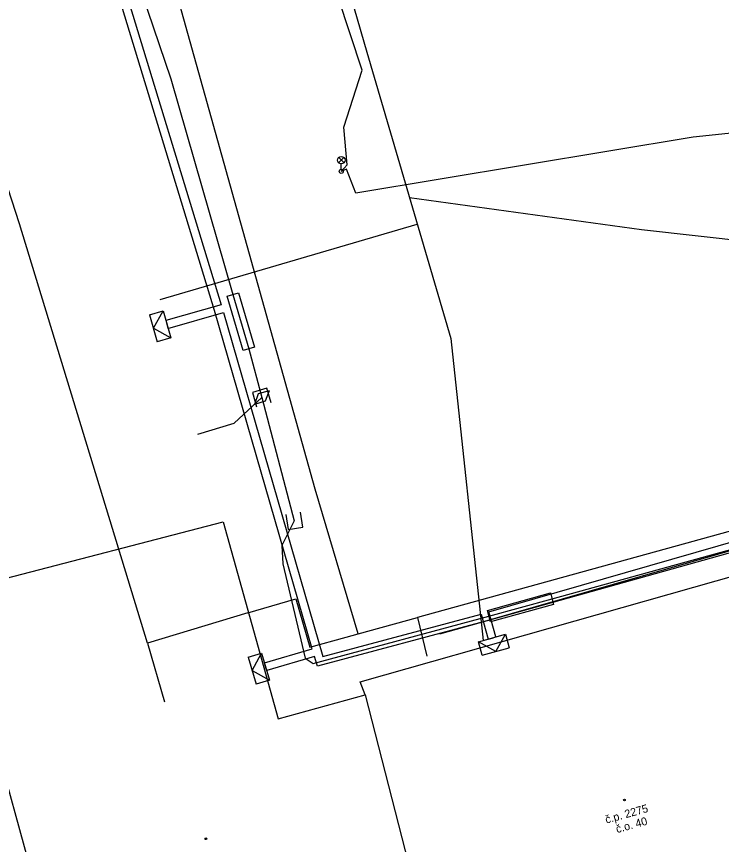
# Model space of a CAD drawing. Extents: x -599432 to -598680, y -1159407 to -1158632.
# Drawn here: x -599223.2 to -599187.97, y -1158918.84 to -1158877.46 of the extents above; entities that cross this region are included whole.
import ezdxf

# ---------------------------------------------------------------- set-up
doc = ezdxf.new("R2010")
doc.units = 0
for name, color, linetype in [('0009 TE - Budova - popis', 7, 'Continuous'), ('0010 ZA - Budova - označení', 7, 'Continuous'), ('0049 TE - Orientační _ popisná čísla', 7, 'Continuous'), ('0116 PV - budova převzatá z mapy', 7, 'Continuous'), ('0350 PV - EON - buňky', 7, 'Continuous'), ('0352 PV - EON - NN', 7, 'Continuous'), ('0400 PV - TSB - buňky', 7, 'Continuous'), ('0407 PV - TSB - kabelové vedení přibližný zákres', 7, 'Continuous'), ('0454 PV - O2 - kabel zaměřený', 7, 'Continuous'), ('0454 PV - PODA -  vedeni budoucnost', 7, 'Continuous'), ('0455 PV - O2 - kabel nezaměřený', 7, 'Continuous'), ('0502 PV - UPC - vedení', 7, 'Continuous'), ('0551 PV - NETBOX - buňky', 7, 'Continuous'), ('0552 PV - NETBOX - vedení', 7, 'Continuous'), ('0553 PV - NETBOX - chranička', 7, 'Continuous')]:
    doc.layers.add(name, color=color, linetype=linetype)

# ---------------------------------------------------------------- blocks, each defined once
blk = doc.blocks.new('NN630')
at = {"layer": '0009 TE - Budova - popis'}
for points in [[(-0.003, -0.7), (-0.703, 0)], [(-0.703, -0.7), (-0.703, 0), (0.697, 0), (0.697, -0.7)], [(-0.003, -0.7), (0.697, 0)], [(-0.703, -0.7), (0.697, -0.7)]]:
    blk.add_lwpolyline(points, dxfattribs=at)

msp = doc.modelspace()

# ---------------------------------------------------------------- linework, layer by layer
at = {"layer": '0010 ZA - Budova - označení'}
for centre in [(-599192.82, -1158916.621), (-599213.736, -1158918.558)]:
    msp.add_circle(centre, 0.0438, dxfattribs=at)
at = {"layer": '0116 PV - budova převzatá z mapy'}
for p, q in [((-599226.34, -1158906.21), (-599212.88, -1158902.72)), ((-599212.88, -1158902.72), (-599210.13, -1158912.56)), ((-599206.02, -1158910.72), (-599185.58, -1158904.91)), ((-599220.88, -1158925.86), (-599226.34, -1158906.21)), ((-599205.78, -1158911.36), (-599206.02, -1158910.72)), ((-599210.13, -1158912.56), (-599205.78, -1158911.36)), ((-599205.78, -1158911.36), (-599203.51, -1158920.21))]:
    msp.add_line(p, q, dxfattribs=at)
at = {"layer": '0352 PV - EON - NN'}
for points in [[(-599127.86, -1158882.798), (-599146.38, -1158888.373), (-599147.226, -1158886.732), (-599148.558, -1158885.917), (-599157.995, -1158888.811), (-599158.229, -1158890.149), (-599156.992, -1158894.185), (-599157.012, -1158894.507), (-599171.99, -1158898.675), (-599171.4, -1158900.819), (-599171.593, -1158900.872), (-599171.786, -1158900.926), (-599172.366, -1158898.821), (-599176.528, -1158900.998), (-599199.817, -1158907.699), (-599208.168, -1158909.938), (-599208.311, -1158909.443), (-599210.7, -1158910.15), (-599210.757, -1158909.958), (-599210.814, -1158909.766), (-599208.422, -1158909.058), (-599213.314, -1158892.15), (-599218.675, -1158874.525)], [(-599218.286, -1158874.431), (-599212.979, -1158891.875), (-599215.744, -1158892.661), (-599215.689, -1158892.854), (-599215.634, -1158893.046), (-599212.865, -1158892.259), (-599207.892, -1158909.45), (-599199.985, -1158907.329), (-599199.632, -1158908.579), (-599199.439, -1158908.525), (-599199.247, -1158908.47), (-599199.6, -1158907.219), (-599176.678, -1158900.624)]]:
    msp.add_lwpolyline(points, dxfattribs=at)
at = {"layer": '0400 PV - TSB - buňky'}
for p, q in [((-599207.103, -1158884.769), (-599206.839, -1158884.505)), ((-599206.835, -1158884.768), (-599207.099, -1158884.503)), ((-599206.971, -1158885.1), (-599206.971, -1158884.825))]:
    msp.add_line(p, q, dxfattribs=at)
for centre, radius in [((-599206.971, -1158884.638), 0.188), ((-599206.971, -1158885.2), 0.1)]:
    msp.add_circle(centre, radius, dxfattribs=at)
at = {"layer": '0407 PV - TSB - kabelové vedení přibližný zákres'}
for p, q in [((-599205.933, -1158880.147), (-599207.451, -1158875.503)), ((-599206.839, -1158882.992), (-599205.933, -1158880.147)), ((-599206.686, -1158884.88), (-599206.839, -1158882.992)), ((-599186.75, -1158883.202), (-599189.379, -1158883.496)), ((-599189.379, -1158883.496), (-599206.239, -1158886.284)), ((-599206.971, -1158885.2), (-599206.686, -1158884.88)), ((-599206.711, -1158885.097), (-599206.971, -1158885.2)), ((-599206.239, -1158886.284), (-599206.711, -1158885.097))]:
    msp.add_line(p, q, dxfattribs=at)
at = {"layer": '0454 PV - O2 - kabel zaměřený'}
for points in [[(-599206.13, -1158908.32), (-599208.27, -1158901.09), (-599222.78, -1158849.14)], [(-599178.89, -1158900.77), (-599186.21, -1158902.82), (-599203.16, -1158907.5)], [(-599211.64, -1158907.26), (-599209.24, -1158906.56), (-599208.54, -1158908.98), (-599206.72, -1158908.48)], [(-599206.13, -1158908.32), (-599203.16, -1158907.5)], [(-599203.16, -1158907.5), (-599202.7, -1158909.44)], [(-599206.72, -1158908.48), (-599206.13, -1158908.32)]]:
    msp.add_lwpolyline(points, dxfattribs=at)
at = {"layer": '0454 PV - PODA -  vedeni budoucnost'}
for p, q in [((-599216.024, -1158891.606), (-599203.176, -1158887.835)), ((-599201.499, -1158893.551), (-599199.885, -1158908.649))]:
    msp.add_line(p, q, dxfattribs=at)
for points in [[(-599213.065, -1158853.829), (-599205.701, -1158879.233), (-599201.499, -1158893.551)], [(-599178.412, -1158889.632), (-599191.972, -1158888.126), (-599203.563, -1158886.519)]]:
    msp.add_lwpolyline(points, dxfattribs=at)
at = {"layer": '0455 PV - O2 - kabel nezaměřený'}
for points in [[(-599223.06, -1158887.82), (-599230.25, -1158865.65)], [(-599216.66, -1158908.78), (-599223.06, -1158887.82)], [(-599211.64, -1158907.26), (-599216.66, -1158908.78)], [(-599216.66, -1158908.78), (-599215.8, -1158911.72)]]:
    msp.add_lwpolyline(points, dxfattribs=at)
at = {"layer": '0502 PV - UPC - vedení'}
msp.add_lwpolyline([(-599070.544, -1158871.051), (-599097.63, -1158878.52), (-599101.81, -1158873.41), (-599105.21, -1158870.19), (-599109.44, -1158870.73), (-599116.17, -1158872.18), (-599160.81, -1158885.76), (-599161.04, -1158886.39), (-599160.77, -1158890.42), (-599159.77, -1158894.71), (-599159.97, -1158895.11), (-599172.93, -1158899.01), (-599176.45, -1158901.16), (-599202.06, -1158908.34)], dxfattribs=at)
at = {"layer": '0551 PV - NETBOX - buňky'}
for points in [[(-599210.482, -1158896.762), (-599210.691, -1158896.042), (-599211.411, -1158896.25), (-599211.203, -1158896.971)], [(-599210.582, -1158896.165), (-599211.122, -1158896.324)], [(-599210.582, -1158896.165), (-599210.772, -1158896.687)], [(-599211.122, -1158896.324), (-599211.313, -1158896.847)], [(-599210.772, -1158896.687), (-599211.313, -1158896.847)], [(-599209.748, -1158902.357), (-599209.633, -1158903.098), (-599208.892, -1158902.982), (-599209.007, -1158902.241)]]:
    msp.add_lwpolyline(points, dxfattribs=at)
at = {"layer": '0552 PV - NETBOX - vedení'}
for points in [[(-599219.671, -1158867.441), (-599218.7, -1158871.09), (-599215.49, -1158880.58), (-599212.39, -1158891.36), (-599211.59, -1158894.07), (-599210.947, -1158896.506)], [(-599209.32, -1158902.67), (-599209.94, -1158903.9), (-599209.9, -1158904.82), (-599208.78, -1158909.53), (-599208.38, -1158909.8), (-599199.59, -1158907.43), (-599196.44, -1158906.56), (-599183.22, -1158902.92), (-599177.19, -1158901.26), (-599176.22, -1158900.88), (-599176.23, -1158900.45), (-599176.04, -1158897.18), (-599175.65, -1158894.8), (-599175.65, -1158894.28), (-599175.49, -1158893.8)], [(-599214.139, -1158898.336), (-599212.33, -1158897.79), (-599210.947, -1158896.506)], [(-599210.947, -1158896.506), (-599209.32, -1158902.67)]]:
    msp.add_lwpolyline(points, dxfattribs=at)
at = {"layer": '0553 PV - NETBOX - chranička'}
for points in [[(-599212.678, -1158891.445), (-599212.102, -1158891.275), (-599211.302, -1158893.985), (-599211.878, -1158894.155)], [(-599199.51, -1158907.719), (-599199.67, -1158907.141), (-599196.52, -1158906.271), (-599196.36, -1158906.849)]]:
    msp.add_lwpolyline(points, close=True, dxfattribs=at)

# ---------------------------------------------------------------- block references
at = {"layer": '0350 PV - EON - buňky'}
for p, rotation in [((-599215.689, -1158892.854), -74.14064441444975), ((-599199.439, -1158908.525), 15.755388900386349), ((-599210.757, -1158909.958), -73.51596391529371)]:
    msp.add_blockref('NN630', p, dxfattribs=dict(at, rotation=rotation))

# ---------------------------------------------------------------- texts
at = {"layer": '0049 TE - Orientační _ popisná čísla'}
for s, p in [('č.p. 2275', (-599193.722, -1158917.804)), ('č.o. 40', (-599193.188, -1158918.278))]:
    msp.add_text(s, height=0.4, rotation=15.6438, dxfattribs=at).set_placement(p)

doc.saveas('drawing.dxf')
